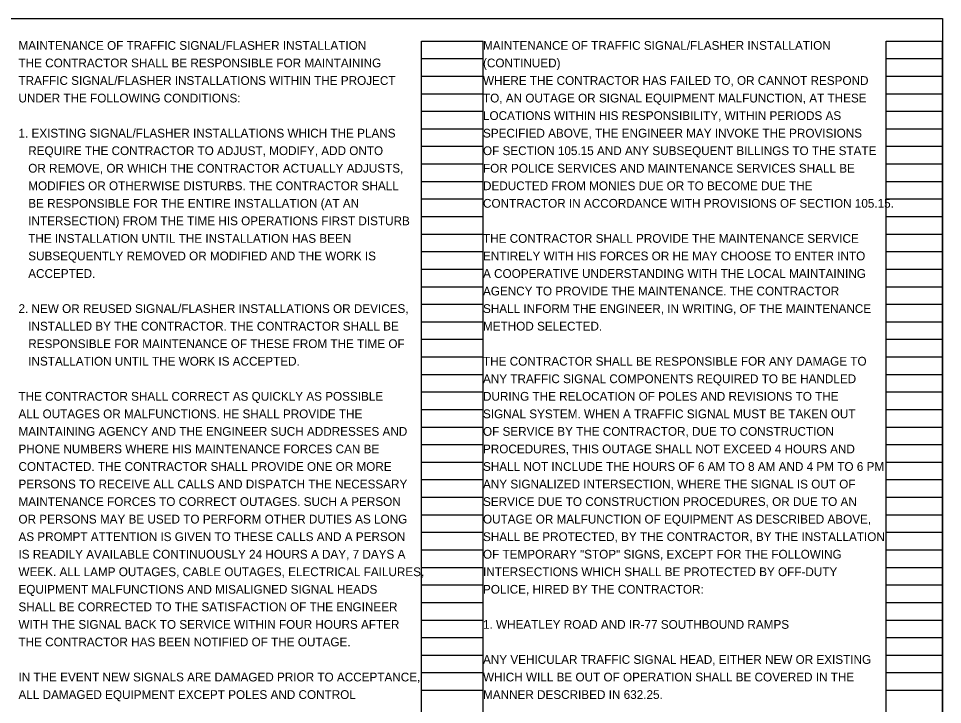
# Model space of a CAD drawing. Extents: x 1820207 to 1820557, y 740216 to 740315.
# Drawn here: x 1820312.97 to 1820327.73, y 740264.79 to 740275.74 of the extents above; entities that cross this region are included whole.
import ezdxf

# ---------------------------------------------------------------- set-up
doc = ezdxf.new("R2010")
doc.units = 0
for name, color, linetype in [('SC_Scratch1', 7, 'Continuous'), ('SC_Scratch2', 7, 'Continuous'), ('SH_Text', 7, 'Continuous')]:
    doc.layers.add(name, color=color, linetype=linetype)

msp = doc.modelspace()

# ---------------------------------------------------------------- linework, layer by layer
at = {"layer": 'SC_Scratch1'}
for p, q in [((1820319.414, 740255.222), (1820319.414, 740275.382)), ((1820319.414, 740275.382), (1820320.394, 740275.382)), ((1820320.394, 740255.222), (1820320.394, 740275.382)), ((1820326.834, 740255.222), (1820326.834, 740275.382)), ((1820326.834, 740275.382), (1820327.734, 740275.382)), ((1820327.734, 740255.222), (1820327.734, 740275.382)), ((1820319.414, 740275.102), (1820320.394, 740275.102)), ((1820326.834, 740275.102), (1820327.734, 740275.102)), ((1820319.414, 740274.822), (1820320.394, 740274.822)), ((1820326.834, 740274.822), (1820327.734, 740274.822)), ((1820319.414, 740274.542), (1820320.394, 740274.542)), ((1820326.834, 740274.542), (1820327.734, 740274.542)), ((1820319.414, 740274.262), (1820320.394, 740274.262)), ((1820326.834, 740274.262), (1820327.734, 740274.262)), ((1820319.414, 740273.982), (1820320.394, 740273.982)), ((1820326.834, 740273.982), (1820327.734, 740273.982)), ((1820319.414, 740273.702), (1820320.394, 740273.702)), ((1820326.834, 740273.702), (1820327.734, 740273.702)), ((1820319.414, 740273.422), (1820320.394, 740273.422)), ((1820326.834, 740273.422), (1820327.734, 740273.422)), ((1820319.414, 740273.142), (1820320.394, 740273.142)), ((1820326.834, 740273.142), (1820327.734, 740273.142)), ((1820319.414, 740272.862), (1820320.394, 740272.862)), ((1820326.834, 740272.862), (1820327.734, 740272.862)), ((1820319.414, 740272.582), (1820320.394, 740272.582)), ((1820326.834, 740272.582), (1820327.734, 740272.582)), ((1820319.414, 740272.302), (1820320.394, 740272.302)), ((1820326.834, 740272.302), (1820327.734, 740272.302)), ((1820319.414, 740272.022), (1820320.394, 740272.022)), ((1820326.834, 740272.022), (1820327.734, 740272.022)), ((1820319.414, 740271.742), (1820320.394, 740271.742)), ((1820326.834, 740271.742), (1820327.734, 740271.742)), ((1820319.414, 740271.462), (1820320.394, 740271.462)), ((1820326.834, 740271.462), (1820327.734, 740271.462)), ((1820319.414, 740271.182), (1820320.394, 740271.182)), ((1820326.834, 740271.182), (1820327.734, 740271.182)), ((1820319.414, 740270.902), (1820320.394, 740270.902)), ((1820326.834, 740270.902), (1820327.734, 740270.902)), ((1820319.414, 740270.622), (1820320.394, 740270.622)), ((1820326.834, 740270.622), (1820327.734, 740270.622)), ((1820319.414, 740270.342), (1820320.394, 740270.342)), ((1820326.834, 740270.342), (1820327.734, 740270.342)), ((1820319.414, 740270.062), (1820320.394, 740270.062)), ((1820326.834, 740270.062), (1820327.734, 740270.062)), ((1820319.414, 740269.782), (1820320.394, 740269.782)), ((1820326.834, 740269.782), (1820327.734, 740269.782)), ((1820319.414, 740269.502), (1820320.394, 740269.502)), ((1820326.834, 740269.502), (1820327.734, 740269.502)), ((1820319.414, 740269.222), (1820320.394, 740269.222)), ((1820326.834, 740269.222), (1820327.734, 740269.222)), ((1820319.414, 740268.942), (1820320.394, 740268.942)), ((1820326.834, 740268.942), (1820327.734, 740268.942)), ((1820319.414, 740268.662), (1820320.394, 740268.662)), ((1820326.834, 740268.662), (1820327.734, 740268.662)), ((1820319.414, 740268.382), (1820320.394, 740268.382)), ((1820326.834, 740268.382), (1820327.734, 740268.382)), ((1820319.414, 740268.102), (1820320.394, 740268.102)), ((1820326.834, 740268.102), (1820327.734, 740268.102)), ((1820319.414, 740267.822), (1820320.394, 740267.822)), ((1820326.834, 740267.822), (1820327.734, 740267.822)), ((1820319.414, 740267.542), (1820320.394, 740267.542)), ((1820326.834, 740267.542), (1820327.734, 740267.542)), ((1820319.414, 740267.262), (1820320.394, 740267.262)), ((1820326.834, 740267.262), (1820327.734, 740267.262)), ((1820319.414, 740266.982), (1820320.394, 740266.982)), ((1820326.834, 740266.982), (1820327.734, 740266.982)), ((1820319.414, 740266.702), (1820320.394, 740266.702)), ((1820326.834, 740266.702), (1820327.734, 740266.702)), ((1820319.414, 740266.422), (1820320.394, 740266.422)), ((1820326.834, 740266.422), (1820327.734, 740266.422)), ((1820319.414, 740266.142), (1820320.394, 740266.142)), ((1820326.834, 740266.142), (1820327.734, 740266.142)), ((1820319.414, 740265.862), (1820320.394, 740265.862)), ((1820326.834, 740265.862), (1820327.734, 740265.862)), ((1820319.414, 740265.582), (1820320.394, 740265.582)), ((1820326.834, 740265.582), (1820327.734, 740265.582)), ((1820319.414, 740265.302), (1820320.394, 740265.302)), ((1820326.834, 740265.302), (1820327.734, 740265.302)), ((1820319.414, 740265.022), (1820320.394, 740265.022)), ((1820326.834, 740265.022), (1820327.734, 740265.022))]:
    msp.add_line(p, q, dxfattribs=at)
at = {"layer": 'SC_Scratch2'}
msp.add_lwpolyline([(1820297.234, 740275.742), (1820327.734, 740275.742), (1820327.734, 740254.742), (1820297.234, 740254.742)], close=True, dxfattribs=at)

# ---------------------------------------------------------------- texts
at = {"layer": 'SH_Text'}
for s, p in [('MAINTENANCE OF TRAFFIC SIGNAL/FLASHER INSTALLATION', (1820312.974, 740275.242)), ('MAINTENANCE OF TRAFFIC SIGNAL/FLASHER INSTALLATION', (1820320.394, 740275.242)), ('THE CONTRACTOR SHALL BE RESPONSIBLE FOR MAINTAINING ', (1820312.974, 740274.962)), ('(CONTINUED)', (1820320.394, 740274.962)), ('TRAFFIC SIGNAL/FLASHER INSTALLATIONS WITHIN THE PROJECT ', (1820312.974, 740274.682)), ('WHERE THE CONTRACTOR HAS FAILED TO, OR CANNOT RESPOND ', (1820320.394, 740274.682)), ('UNDER THE FOLLOWING CONDITIONS:', (1820312.974, 740274.402)), ('TO, AN OUTAGE OR SIGNAL EQUIPMENT MALFUNCTION, AT THESE', (1820320.394, 740274.402)), ('LOCATIONS WITHIN HIS RESPONSIBILITY, WITHIN PERIODS AS ', (1820320.394, 740274.122)), ('1. EXISTING SIGNAL/FLASHER INSTALLATIONS WHICH THE PLANS ', (1820312.974, 740273.842)), ('SPECIFIED ABOVE, THE ENGINEER MAY INVOKE THE PROVISIONS ', (1820320.394, 740273.842)), ('   REQUIRE THE CONTRACTOR TO ADJUST, MODIFY, ADD ONTO ', (1820312.974, 740273.562)), ('OF SECTION 105.15 AND ANY SUBSEQUENT BILLINGS TO THE STATE ', (1820320.394, 740273.562)), ('   OR REMOVE, OR WHICH THE CONTRACTOR ACTUALLY ADJUSTS, ', (1820312.974, 740273.282)), ('FOR POLICE SERVICES AND MAINTENANCE SERVICES SHALL BE ', (1820320.394, 740273.282)), ('   MODIFIES OR OTHERWISE DISTURBS. THE CONTRACTOR SHALL ', (1820312.974, 740273.002)), ('DEDUCTED FROM MONIES DUE OR TO BECOME DUE THE ', (1820320.394, 740273.002)), ('   BE RESPONSIBLE FOR THE ENTIRE INSTALLATION (AT AN ', (1820312.974, 740272.722)), ('CONTRACTOR IN ACCORDANCE WITH PROVISIONS OF SECTION 105.15.', (1820320.394, 740272.722)), ('   INTERSECTION) FROM THE TIME HIS OPERATIONS FIRST DISTURB ', (1820312.974, 740272.442)), ('   THE INSTALLATION UNTIL THE INSTALLATION HAS BEEN ', (1820312.974, 740272.162)), ('THE CONTRACTOR SHALL PROVIDE THE MAINTENANCE SERVICE ', (1820320.394, 740272.162)), ('   SUBSEQUENTLY REMOVED OR MODIFIED AND THE WORK IS', (1820312.974, 740271.882)), ('ENTIRELY WITH HIS FORCES OR HE MAY CHOOSE TO ENTER INTO ', (1820320.394, 740271.882)), ('   ACCEPTED.', (1820312.974, 740271.602)), ('A COOPERATIVE UNDERSTANDING WITH THE LOCAL MAINTAINING ', (1820320.394, 740271.602)), ('AGENCY TO PROVIDE THE MAINTENANCE. THE CONTRACTOR ', (1820320.394, 740271.322)), ('2. NEW OR REUSED SIGNAL/FLASHER INSTALLATIONS OR DEVICES, ', (1820312.974, 740271.042)), ('SHALL INFORM THE ENGINEER, IN WRITING, OF THE MAINTENANCE ', (1820320.394, 740271.042)), ('   INSTALLED BY THE CONTRACTOR. THE CONTRACTOR SHALL BE', (1820312.974, 740270.762)), ('METHOD SELECTED.', (1820320.394, 740270.762)), ('   RESPONSIBLE FOR MAINTENANCE OF THESE FROM THE TIME OF ', (1820312.974, 740270.482)), ('   INSTALLATION UNTIL THE WORK IS ACCEPTED. ', (1820312.974, 740270.202)), ('THE CONTRACTOR SHALL BE RESPONSIBLE FOR ANY DAMAGE TO ', (1820320.394, 740270.202)), ('ANY TRAFFIC SIGNAL COMPONENTS REQUIRED TO BE HANDLED ', (1820320.394, 740269.922)), ('THE CONTRACTOR SHALL CORRECT AS QUICKLY AS POSSIBLE ', (1820312.974, 740269.642)), ('DURING THE RELOCATION OF POLES AND REVISIONS TO THE ', (1820320.394, 740269.642)), ('ALL OUTAGES OR MALFUNCTIONS. HE SHALL PROVIDE THE ', (1820312.974, 740269.362)), ('SIGNAL SYSTEM. WHEN A TRAFFIC SIGNAL MUST BE TAKEN OUT ', (1820320.394, 740269.362)), ('MAINTAINING AGENCY AND THE ENGINEER SUCH ADDRESSES AND ', (1820312.974, 740269.082)), ('OF SERVICE BY THE CONTRACTOR, DUE TO CONSTRUCTION ', (1820320.394, 740269.082)), ('PHONE NUMBERS WHERE HIS MAINTENANCE FORCES CAN BE ', (1820312.974, 740268.802)), ('PROCEDURES, THIS OUTAGE SHALL NOT EXCEED 4 HOURS AND ', (1820320.394, 740268.802)), ('CONTACTED. THE CONTRACTOR SHALL PROVIDE ONE OR MORE ', (1820312.974, 740268.522)), ('SHALL NOT INCLUDE THE HOURS OF 6 AM TO 8 AM AND 4 PM TO 6 PM. ', (1820320.394, 740268.522)), ('PERSONS TO RECEIVE ALL CALLS AND DISPATCH THE NECESSARY ', (1820312.974, 740268.242)), ('ANY SIGNALIZED INTERSECTION, WHERE THE SIGNAL IS OUT OF ', (1820320.394, 740268.242)), ('MAINTENANCE FORCES TO CORRECT OUTAGES. SUCH A PERSON ', (1820312.974, 740267.962)), ('SERVICE DUE TO CONSTRUCTION PROCEDURES, OR DUE TO AN ', (1820320.394, 740267.962)), ('OR PERSONS MAY BE USED TO PERFORM OTHER DUTIES AS LONG ', (1820312.974, 740267.682)), ('OUTAGE OR MALFUNCTION OF EQUIPMENT AS DESCRIBED ABOVE, ', (1820320.394, 740267.682)), ('AS PROMPT ATTENTION IS GIVEN TO THESE CALLS AND A PERSON ', (1820312.974, 740267.402)), ('SHALL BE PROTECTED, BY THE CONTRACTOR, BY THE INSTALLATION ', (1820320.394, 740267.402)), ('IS READILY AVAILABLE CONTINUOUSLY 24 HOURS A DAY, 7 DAYS A ', (1820312.974, 740267.122)), ('OF TEMPORARY "STOP" SIGNS, EXCEPT FOR THE FOLLOWING ', (1820320.394, 740267.122)), ('WEEK. ALL LAMP OUTAGES, CABLE OUTAGES, ELECTRICAL FAILURES, ', (1820312.974, 740266.842)), ('INTERSECTIONS WHICH SHALL BE PROTECTED BY OFF-DUTY ', (1820320.394, 740266.842)), ('EQUIPMENT MALFUNCTIONS AND MISALIGNED SIGNAL HEADS ', (1820312.974, 740266.562)), ('POLICE, HIRED BY THE CONTRACTOR:', (1820320.394, 740266.562)), ('SHALL BE CORRECTED TO THE SATISFACTION OF THE ENGINEER ', (1820312.974, 740266.282)), ('WITH THE SIGNAL BACK TO SERVICE WITHIN FOUR HOURS AFTER ', (1820312.974, 740266.002)), ('1. WHEATLEY ROAD AND IR-77 SOUTHBOUND RAMPS', (1820320.394, 740266.002)), ('THE CONTRACTOR HAS BEEN NOTIFIED OF THE OUTAGE.', (1820312.974, 740265.722)), ('ANY VEHICULAR TRAFFIC SIGNAL HEAD, EITHER NEW OR EXISTING ', (1820320.394, 740265.442)), ('IN THE EVENT NEW SIGNALS ARE DAMAGED PRIOR TO ACCEPTANCE, ', (1820312.974, 740265.162)), ('WHICH WILL BE OUT OF OPERATION SHALL BE COVERED IN THE', (1820320.394, 740265.162)), ('ALL DAMAGED EQUIPMENT EXCEPT POLES AND CONTROL ', (1820312.974, 740264.882)), ('MANNER DESCRIBED IN 632.25.', (1820320.394, 740264.882))]:
    msp.add_text(s, height=0.14, dxfattribs=at).set_placement(p)

doc.saveas('drawing.dxf')
